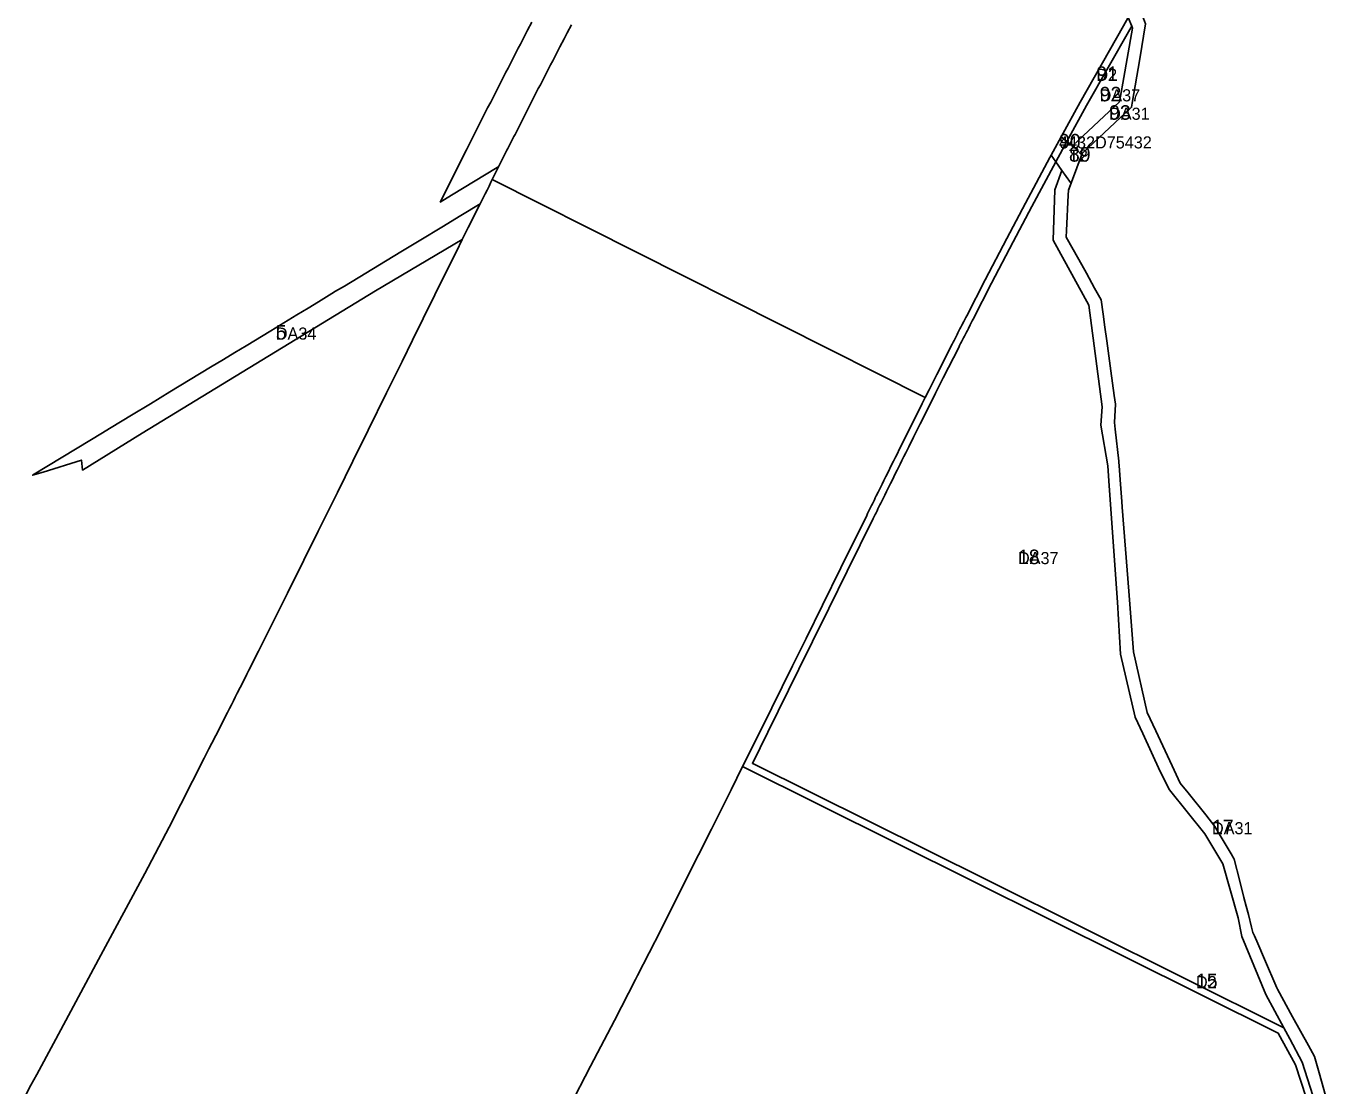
# Model space of a CAD drawing. Extents: x -537012 to -534603, y -1176562 to -1172739.
# Drawn here: x -536124 to -535587, y -1174132 to -1173694 of the extents above; entities that cross this region are included whole.
import ezdxf

# ---------------------------------------------------------------- set-up
doc = ezdxf.new("R2010")
doc.units = 0
for name, color, linetype in [('96120023', 7, 'Continuous'), ('96140023', 7, 'Continuous'), ('ID_VPO', 7, 'Continuous'), ('ID_VPS', 7, 'Continuous')]:
    doc.layers.add(name, color=color, linetype=linetype)

msp = doc.modelspace()

# ---------------------------------------------------------------- linework, layer by layer
at = {"layer": '96120023'}
for points in [[(-535671.6, -1173694.36), (-535689.54, -1173725.83), (-535697.41, -1173740.24), (-535701.53, -1173747.78), (-535702.04, -1173748.72), (-535712.13, -1173767.54), (-535719.86, -1173782.15), (-535728.74, -1173799.17), (-535736.36, -1173813.97), (-535736.76, -1173814.75), (-535737.16, -1173815.53), (-535737.56, -1173816.31), (-535738.36, -1173817.87), (-535738.76, -1173818.66), (-535739.16, -1173819.44), (-535739.55, -1173820.22), (-535739.95, -1173821.01), (-535740.35, -1173821.79), (-535740.75, -1173822.57), (-535741.15, -1173823.36), (-535741.55, -1173824.14), (-535741.95, -1173824.92), (-535742.35, -1173825.71), (-535748.71, -1173838.29), (-535751.89, -1173844.6), (-535753.49, -1173847.78), (-535932.12, -1173757.82), (-535931.97, -1173757.52), (-535931.81, -1173757.21), (-535931.4, -1173756.39), (-535930.99, -1173755.58), (-535930.58, -1173754.76), (-535930.17, -1173753.94), (-535929.75, -1173753.12), (-535929.5, -1173752.61), (-535929.43, -1173752.48), (-535929.34, -1173752.3), (-535928.93, -1173751.48), (-535928.52, -1173750.66), (-535928.1, -1173749.84), (-535927.69, -1173749.02), (-535927.28, -1173748.2), (-535926.87, -1173747.39), (-535926.45, -1173746.57), (-535926.04, -1173745.75), (-535925.62, -1173744.93), (-535925.21, -1173744.11), (-535924.8, -1173743.29), (-535924.38, -1173742.47), (-535923.97, -1173741.65), (-535923.55, -1173740.83), (-535923.14, -1173740.01), (-535922.72, -1173739.19), (-535921.47, -1173736.73), (-535920.64, -1173735.09), (-535919.39, -1173732.63), (-535918.13, -1173730.16), (-535916.88, -1173727.7), (-535916.04, -1173726.06), (-535915.2, -1173724.42), (-535913.94, -1173721.96), (-535913.1, -1173720.31), (-535912.25, -1173718.67), (-535911.41, -1173717.03), (-535910.56, -1173715.38), (-535909.72, -1173713.74), (-535908.87, -1173712.1), (-535908.02, -1173710.45), (-535907.17, -1173708.81), (-535905.89, -1173706.34), (-535904.19, -1173703.06), (-535902.48, -1173699.77), (-535901.19, -1173697.3), (-535899.47, -1173694.01)], [(-535596.36, -1174136.54), (-535600.68, -1174123.06), (-535607.79, -1174109.96), (-535828.81, -1174000.01), (-535821.06, -1173984.4), (-535808.24, -1173958.45), (-535802.65, -1173947.12), (-535795.88, -1173933.37), (-535788.33, -1173918.03), (-535777.63, -1173896.33), (-535777.23, -1173895.52), (-535776.83, -1173894.72), (-535776.44, -1173893.92), (-535776.04, -1173893.12), (-535775.65, -1173892.32), (-535775.25, -1173891.52), (-535774.86, -1173890.72), (-535774.46, -1173889.92), (-535774.06, -1173889.12), (-535773.67, -1173888.32), (-535772.88, -1173886.72), (-535772.09, -1173885.12), (-535771.29, -1173883.52), (-535770.5, -1173881.92), (-535769.71, -1173880.33), (-535768.53, -1173877.93), (-535767.73, -1173876.34), (-535766.55, -1173873.95), (-535765.76, -1173872.35), (-535764.96, -1173870.76), (-535764.17, -1173869.17), (-535762.99, -1173866.78), (-535761.01, -1173862.81), (-535758.23, -1173857.25), (-535754.67, -1173850.13), (-535753.49, -1173847.78), (-535751.89, -1173844.6), (-535748.71, -1173838.29), (-535742.35, -1173825.71), (-535741.95, -1173824.92), (-535741.55, -1173824.14), (-535741.15, -1173823.36), (-535740.75, -1173822.57), (-535740.35, -1173821.79), (-535739.95, -1173821.01), (-535739.55, -1173820.22), (-535739.16, -1173819.44), (-535738.76, -1173818.66), (-535738.36, -1173817.87), (-535737.56, -1173816.31), (-535737.16, -1173815.53), (-535736.76, -1173814.75), (-535736.36, -1173813.97), (-535728.74, -1173799.17), (-535719.86, -1173782.15), (-535712.13, -1173767.54), (-535702.04, -1173748.72), (-535701.53, -1173747.78), (-535699.59, -1173750.49), (-535709.48, -1173768.95), (-535717.2, -1173783.55), (-535726.08, -1173800.55), (-535733.69, -1173815.34), (-535734.09, -1173816.12), (-535734.49, -1173816.9), (-535734.89, -1173817.68), (-535735.68, -1173819.24), (-535736.08, -1173820.02), (-535736.48, -1173820.8), (-535737.28, -1173822.37), (-535737.68, -1173823.15), (-535738.08, -1173823.93), (-535738.48, -1173824.72), (-535738.88, -1173825.5), (-535739.27, -1173826.28), (-535739.67, -1173827.06), (-535746.04, -1173839.64), (-535749.21, -1173845.94), (-535752.16, -1173851.81), (-535755.55, -1173858.6), (-535758.32, -1173864.15), (-535760.3, -1173868.12), (-535761.49, -1173870.5), (-535762.28, -1173872.1), (-535763.07, -1173873.69), (-535763.86, -1173875.28), (-535765.05, -1173877.67), (-535765.84, -1173879.26), (-535767.02, -1173881.66), (-535767.81, -1173883.25), (-535768.61, -1173884.85), (-535769.4, -1173886.45), (-535770.19, -1173888.05), (-535770.98, -1173889.65), (-535771.37, -1173890.45), (-535771.77, -1173891.25), (-535772.17, -1173892.05), (-535772.56, -1173892.85), (-535772.96, -1173893.65), (-535773.35, -1173894.45), (-535773.75, -1173895.25), (-535774.14, -1173896.05), (-535774.54, -1173896.85), (-535774.94, -1173897.65), (-535785.64, -1173919.36), (-535793.19, -1173934.7), (-535799.96, -1173948.44), (-535805.55, -1173959.78), (-535818.37, -1173985.73), (-535824.79, -1173998.66), (-535824.34, -1173998.89), (-535728.12, -1174046.76), (-535605.58, -1174107.71), (-535603.1, -1174112.3), (-535597.91, -1174121.88), (-535593.49, -1174135.66)], [(-536124.46, -1174135.08), (-536122.45, -1174131.35), (-536120.06, -1174127.01), (-536113.09, -1174114.23), (-536093.59, -1174077.8), (-536075.49, -1174044.05), (-536065.47, -1174024.98), (-536050.99, -1173996.56), (-536048.98, -1173992.62), (-536047.77, -1173990.26), (-536046.16, -1173987.11), (-536044.55, -1173983.96), (-536042.95, -1173980.8), (-536041.34, -1173977.64), (-536040.54, -1173976.06), (-536039.74, -1173974.48), (-536038.93, -1173972.9), (-536038.13, -1173971.32), (-536037.33, -1173969.74), (-536036.13, -1173967.36), (-536034.93, -1173964.99), (-536033.33, -1173961.82), (-536032.53, -1173960.23), (-536030.93, -1173957.06), (-536029.73, -1173954.68), (-536028.54, -1173952.3), (-536023.35, -1173941.97), (-536016.58, -1173928.44), (-536009.83, -1173914.87), (-536003.87, -1173902.88), (-535995.94, -1173886.85), (-535989.59, -1173874), (-535983.24, -1173861.13), (-535975.7, -1173845.81), (-535969.34, -1173832.9), (-535964.95, -1173824), (-535960.56, -1173815.08), (-535955.75, -1173805.34), (-535951.33, -1173796.4), (-535946.89, -1173787.44), (-535944.47, -1173782.56), (-535942.03, -1173777.65), (-535937.55, -1173768.66), (-535937.25, -1173768.07), (-535937.15, -1173767.87), (-535936.73, -1173767.03), (-535935.91, -1173765.39), (-535935.09, -1173763.76), (-535934.27, -1173762.12), (-535933.45, -1173760.49), (-535932.63, -1173758.85), (-535932.12, -1173757.82), (-535753.49, -1173847.78), (-535754.67, -1173850.13), (-535758.23, -1173857.25), (-535761.01, -1173862.81), (-535762.99, -1173866.78), (-535764.17, -1173869.17), (-535764.96, -1173870.76), (-535765.76, -1173872.35), (-535766.55, -1173873.95), (-535767.73, -1173876.34), (-535768.53, -1173877.93), (-535769.71, -1173880.33), (-535770.5, -1173881.92), (-535771.29, -1173883.52), (-535772.09, -1173885.12), (-535772.88, -1173886.72), (-535773.67, -1173888.32), (-535774.06, -1173889.12), (-535774.46, -1173889.92), (-535774.86, -1173890.72), (-535775.25, -1173891.52), (-535775.65, -1173892.32), (-535776.04, -1173893.12), (-535776.44, -1173893.92), (-535776.83, -1173894.72), (-535777.23, -1173895.52), (-535777.63, -1173896.33), (-535788.33, -1173918.03), (-535795.88, -1173933.37), (-535802.65, -1173947.12), (-535808.24, -1173958.45), (-535821.06, -1173984.4), (-535828.81, -1174000.01), (-535833.57, -1174009.59), (-535841.68, -1174025.86), (-535852.31, -1174047.03), (-535862.61, -1174067.4), (-535872.17, -1174086.14), (-535873, -1174087.77), (-535881.74, -1174104.71), (-535891.53, -1174123.6), (-535900.28, -1174140.39)]]:
    msp.add_lwpolyline(points, dxfattribs=at)
for points in [[(-535686.92, -1173727.29), (-535695.05, -1173742.16), (-535697.41, -1173740.24), (-535689.54, -1173725.83), (-535671.6, -1173694.36), (-535669.68, -1173691), (-535668.29, -1173694.6), (-535668.99, -1173695.85)], [(-535697.41, -1173740.24), (-535695.05, -1173742.16), (-535699.59, -1173750.49), (-535701.53, -1173747.78)], [(-535697.05, -1173754.05), (-535699.59, -1173750.49), (-535695.05, -1173742.16), (-535694.65, -1173742.49), (-535692.64, -1173743.73), (-535689.01, -1173747.62), (-535688.76, -1173747.02), (-535690.95, -1173752.98), (-535694.35, -1173762.25), (-535693.31, -1173759.31), (-535693.54, -1173758.96)]]:
    msp.add_lwpolyline(points, close=True, dxfattribs=at)
at = {"layer": '96140023'}
for points in [[(-535689.01, -1173747.62), (-535692.64, -1173743.73), (-535673.33, -1173725.68), (-535671.95, -1173718.08), (-535667.97, -1173695.42), (-535668.29, -1173694.6), (-535669.68, -1173691), (-535668.4, -1173688.75), (-535666.09, -1173684.66), (-535663.42, -1173691.33), (-535662.56, -1173693.55), (-535664.98, -1173708.05), (-535668.03, -1173726.35), (-535668.3, -1173727.97), (-535688.76, -1173747.02)], [(-535667.97, -1173695.42), (-535671.95, -1173718.08), (-535673.33, -1173725.68), (-535692.64, -1173743.73), (-535694.65, -1173742.49), (-535695.05, -1173742.16), (-535686.92, -1173727.29), (-535668.99, -1173695.85), (-535668.29, -1173694.6)], [(-535699.59, -1173750.49), (-535697.05, -1173754.05), (-535700.01, -1173762), (-535700.71, -1173782.81), (-535686.02, -1173809.63), (-535680.41, -1173851.56), (-535681.01, -1173859.2), (-535678.16, -1173875.97), (-535677.62, -1173884.09), (-535674.12, -1173932.13), (-535672.91, -1173953.63), (-535666.8, -1173979.63), (-535663.65, -1173986.37), (-535656.49, -1174001.97), (-535652.66, -1174009.5), (-535638.06, -1174027.71), (-535630.74, -1174040.13), (-535624.39, -1174062.44), (-535622.88, -1174070.09), (-535612.99, -1174094.02), (-535605.58, -1174107.71), (-535728.12, -1174046.76), (-535824.34, -1173998.89), (-535824.79, -1173998.66), (-535818.37, -1173985.73), (-535805.55, -1173959.78), (-535799.96, -1173948.44), (-535793.19, -1173934.7), (-535785.64, -1173919.36), (-535774.94, -1173897.65), (-535774.54, -1173896.85), (-535774.14, -1173896.05), (-535773.75, -1173895.25), (-535773.35, -1173894.45), (-535772.96, -1173893.65), (-535772.56, -1173892.85), (-535772.17, -1173892.05), (-535771.77, -1173891.25), (-535771.37, -1173890.45), (-535770.98, -1173889.65), (-535770.19, -1173888.05), (-535769.4, -1173886.45), (-535768.61, -1173884.85), (-535767.81, -1173883.25), (-535767.02, -1173881.66), (-535765.84, -1173879.26), (-535765.05, -1173877.67), (-535763.86, -1173875.28), (-535763.07, -1173873.69), (-535762.28, -1173872.1), (-535761.49, -1173870.5), (-535760.3, -1173868.12), (-535758.32, -1173864.15), (-535755.55, -1173858.6), (-535752.16, -1173851.81), (-535749.21, -1173845.94), (-535746.04, -1173839.64), (-535739.67, -1173827.06), (-535739.27, -1173826.28), (-535738.88, -1173825.5), (-535738.48, -1173824.72), (-535738.08, -1173823.93), (-535737.68, -1173823.15), (-535737.28, -1173822.37), (-535736.48, -1173820.8), (-535736.08, -1173820.02), (-535735.68, -1173819.24), (-535734.89, -1173817.68), (-535734.49, -1173816.9), (-535734.09, -1173816.12), (-535733.69, -1173815.34), (-535726.08, -1173800.55), (-535717.2, -1173783.55), (-535709.48, -1173768.95)], [(-535937.15, -1173767.87), (-535937.25, -1173768.07), (-535937.55, -1173768.66), (-535942.03, -1173777.65), (-535944.47, -1173782.56), (-535980.23, -1173803.73), (-536076.51, -1173862.38), (-536101.12, -1173877.67), (-536101.58, -1173873.52), (-536117.44, -1173878.48), (-536121.73, -1173879.82), (-536097.5, -1173865.11), (-536093.61, -1173862.75), (-536089.33, -1173860.15), (-536080.97, -1173855.07), (-536073.11, -1173850.3), (-536065.07, -1173845.42), (-536048.32, -1173835.25), (-536042.95, -1173831.99), (-536038.31, -1173829.17), (-536033.67, -1173826.35), (-536023.5, -1173820.17), (-536012.78, -1173813.66), (-536008.07, -1173810.8), (-536003.86, -1173808.25), (-535998.32, -1173804.88), (-535996.73, -1173803.91), (-535993.13, -1173801.73), (-535969.79, -1173787.62), (-535965.74, -1173785.17), (-535961.54, -1173782.63), (-535952.93, -1173777.42), (-535945.08, -1173772.67)]]:
    msp.add_lwpolyline(points, close=True, dxfattribs=at)
for points in [[(-535899.47, -1173694.01), (-535901.19, -1173697.3), (-535902.48, -1173699.77), (-535904.19, -1173703.06), (-535905.89, -1173706.34), (-535907.17, -1173708.81), (-535908.02, -1173710.45), (-535908.87, -1173712.1), (-535909.72, -1173713.74), (-535910.56, -1173715.38), (-535911.41, -1173717.03), (-535912.25, -1173718.67), (-535913.1, -1173720.31), (-535913.94, -1173721.96), (-535915.2, -1173724.42), (-535916.04, -1173726.06), (-535916.88, -1173727.7), (-535918.13, -1173730.16), (-535919.39, -1173732.63), (-535920.64, -1173735.09), (-535921.47, -1173736.73), (-535922.72, -1173739.19), (-535923.14, -1173740.01), (-535923.55, -1173740.83), (-535923.97, -1173741.65), (-535924.38, -1173742.47), (-535924.8, -1173743.29), (-535925.21, -1173744.11), (-535925.62, -1173744.93), (-535926.04, -1173745.75), (-535926.45, -1173746.57), (-535926.87, -1173747.39), (-535927.28, -1173748.2), (-535927.69, -1173749.02), (-535928.1, -1173749.84), (-535928.52, -1173750.66), (-535928.93, -1173751.48), (-535929.34, -1173752.3), (-535929.43, -1173752.48), (-535930.06, -1173752.86), (-535948.96, -1173764.29), (-535953.57, -1173767.08), (-535942.74, -1173745.56), (-535942.33, -1173744.74), (-535941.91, -1173743.91), (-535941.5, -1173743.09), (-535941.09, -1173742.27), (-535940.67, -1173741.45), (-535940.26, -1173740.63), (-535939.84, -1173739.81), (-535939.43, -1173738.98), (-535939.01, -1173738.16), (-535938.6, -1173737.34), (-535938.18, -1173736.52), (-535937.77, -1173735.7), (-535937.35, -1173734.87), (-535936.93, -1173734.05), (-535936.52, -1173733.23), (-535936.1, -1173732.41), (-535934.85, -1173729.94), (-535934.01, -1173728.29), (-535932.76, -1173725.82), (-535931.5, -1173723.35), (-535930.24, -1173720.88), (-535929.4, -1173719.23), (-535928.55, -1173717.59), (-535927.29, -1173715.11), (-535926.44, -1173713.47), (-535925.6, -1173711.82), (-535924.75, -1173710.17), (-535923.9, -1173708.52), (-535923.05, -1173706.87), (-535922.2, -1173705.22), (-535921.35, -1173703.57), (-535920.49, -1173701.92), (-535919.21, -1173699.44), (-535917.5, -1173696.14), (-535915.78, -1173692.84)], [(-535593.49, -1174135.66), (-535597.91, -1174121.88), (-535603.1, -1174112.3), (-535605.58, -1174107.71), (-535612.99, -1174094.02), (-535622.88, -1174070.09), (-535624.39, -1174062.44), (-535630.74, -1174040.13), (-535638.06, -1174027.71), (-535652.66, -1174009.5), (-535656.49, -1174001.97), (-535663.65, -1173986.37), (-535666.8, -1173979.63), (-535672.91, -1173953.63), (-535674.12, -1173932.13), (-535677.62, -1173884.09), (-535678.16, -1173875.97), (-535681.01, -1173859.2), (-535680.41, -1173851.56), (-535686.02, -1173809.63), (-535700.71, -1173782.81), (-535700.01, -1173762), (-535697.05, -1173754.05), (-535693.54, -1173758.96), (-535693.31, -1173759.31), (-535694.35, -1173762.25), (-535694.45, -1173764.25), (-535695.15, -1173778.81), (-535695.28, -1173781.53), (-535690.11, -1173790.84), (-535686.98, -1173796.48), (-535683.59, -1173802.59), (-535680.9, -1173807.44), (-535680.09, -1173813.33), (-535679.35, -1173818.68), (-535678.57, -1173824.37), (-535676.87, -1173836.7), (-535675.47, -1173846.86), (-535674.97, -1173850.53), (-535675.37, -1173858.05), (-535675.08, -1173860.72), (-535673.63, -1173873.95), (-535673.58, -1173874.6), (-535673.49, -1173875.79), (-535673.04, -1173881.63), (-535672.35, -1173890.56), (-535672.17, -1173892.95), (-535669.5, -1173927.55), (-535667.57, -1173952.61), (-535661.87, -1173977.65), (-535658.36, -1173985.16), (-535651.57, -1173999.71), (-535648.27, -1174006.76), (-535645.01, -1174010.83), (-535637.75, -1174019.91), (-535633.96, -1174024.65), (-535632.16, -1174027.72), (-535627.31, -1174035.98), (-535626.01, -1174038.2), (-535623.68, -1174047.25), (-535621.96, -1174053.94), (-535621.02, -1174057.59), (-535620.15, -1174060.99), (-535618.79, -1174066.25), (-535618.25, -1174068.37), (-535617.67, -1174069.74), (-535616.27, -1174073.01), (-535613.52, -1174079.48), (-535608.47, -1174091.3), (-535608.17, -1174091.85), (-535601.9, -1174103.21), (-535595.39, -1174115.02), (-535592.88, -1174119.58), (-535590.94, -1174126.38), (-535587.31, -1174139.14)]]:
    msp.add_lwpolyline(points, dxfattribs=at)

# ---------------------------------------------------------------- texts
at = {"layer": '96120023'}
for s, rotation, p in [('D2', 360, (-535682.85, -1173717.12)), ('4432D75432', 360, (-535698.29, -1173744.98)), ('T2', 360, (-535694.17, -1173750.43)), ('D2', 0, (-535641.77, -1174091.39))]:
    msp.add_text(s, height=5, rotation=rotation, dxfattribs=at).set_placement(p)
at = {"layer": '96140023'}
for s, rotation, p in [('DA37', 360, (-535681.51, -1173725.56)), ('DA31', 360, (-535677.6, -1173733.15)), ('DA34', 360, (-536021.4, -1173823.84)), ('DA37', 0, (-535715.19, -1173916.47)), ('DA31', 360, (-535635.16, -1174027.9))]:
    msp.add_text(s, height=5, rotation=rotation, dxfattribs=at).set_placement(p)
at = {"layer": 'ID_VPO'}
for s, rotation, p in [('92', 0, (-535681.51, -1173725.56)), ('93', 360, (-535677.6, -1173733.15)), ('5', 360, (-536021.4, -1173823.84)), ('18', 0, (-535715.19, -1173916.47)), ('17', 0, (-535635.16, -1174027.9))]:
    msp.add_text(s, height=6, rotation=rotation, dxfattribs=at).set_placement(p)
at = {"layer": 'ID_VPS'}
for s, rotation, p in [('91', 360, (-535682.85, -1173717.12)), ('90', 360, (-535698.29, -1173744.98)), ('89', 360, (-535694.17, -1173750.43)), ('15', 0, (-535641.77, -1174091.39))]:
    msp.add_text(s, height=6, rotation=rotation, dxfattribs=at).set_placement(p)

doc.saveas('drawing.dxf')
